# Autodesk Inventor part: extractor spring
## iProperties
Created: 2006-04
Part Number: extractor spring
Document SubType Name: Modeling
Designer: Калинин
Author: Калинин
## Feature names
1. Пружина1
